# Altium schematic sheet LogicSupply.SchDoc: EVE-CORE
size A4; Organization: Ingenia Motion Control; Address1: Carrer Avila, 124, 2B; Address2: 08018 Barcelona Spain; Address3: www.ingeniamc.com; Address4: www.ingeniamc.com; Documentation: https://doc.ingeniamc.com/x/coAZBg
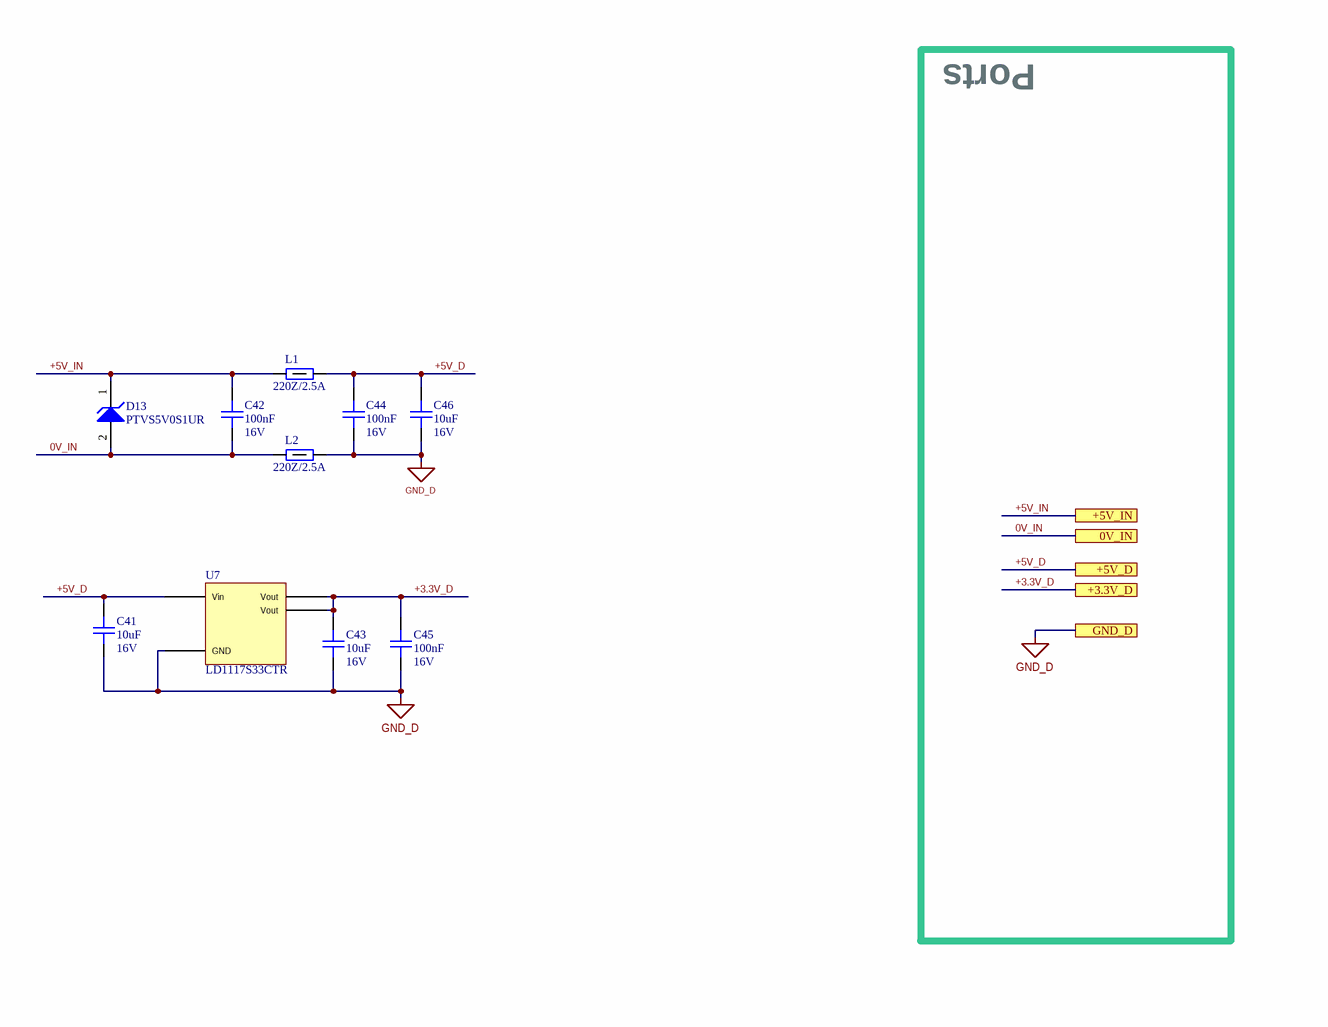
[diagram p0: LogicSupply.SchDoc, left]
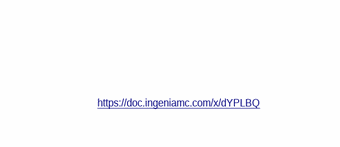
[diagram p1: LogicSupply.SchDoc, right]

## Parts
C41  value 10uF  Voltage: 16V  [C_0805]  (hidden comment: C_0805--10uF--16V)
C42  value 100nF  Voltage: 16V  [C_0402HD]  (hidden comment: C_0402--100nF--16V)
C43  value 10uF  Voltage: 16V  [C_0805]  (hidden comment: C_0805--10uF--16V)
C44  value 100nF  Voltage: 16V  [C_0402HD]  (hidden comment: C_0402--100nF--16V)
C45  value 100nF  Voltage: 16V  [C_0402]  (hidden comment: C_0402--100nF--16V)
C46  value 10uF  Voltage: 16V  [C_0805]  (hidden comment: C_0805--10uF--16V)
D13  Part Number: PTVS5V0S1UR  [SOD123W2]  (hidden comment: TVS2)
L1  value 220Z/2.5A  [L_0603]
L2  value 220Z/2.5A  [L_0603]
U7  LD1117S33CTR  [SOT223-4N]

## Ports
0V_IN, +3.3V_D, +5V_D, +5V_IN, GND_D

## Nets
GND_D: C41.2 C43.2 C44.1 C45.2 C46.2 L2.2 U7.1(GND) ; port GND_D
0V_IN: C42.1 D13.2(A) L2.1 ; port 0V_IN
+3.3V_D: C43.1 C45.1 U7.2(Vout) U7.4(Vout) ; port +3.3V_D
+5V_D: C41.1 C44.2 C46.1 L1.2 U7.3(Vin) ; port +5V_D
+5V_IN: C42.2 D13.1(K) L1.1 ; port +5V_IN

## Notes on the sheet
- Ports
- https://doc.ingeniamc.com/x/dYPLBQ

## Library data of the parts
C41 C43 C46 = C_0805[[/\]]10uF[[/\]]16V: CAP 10 uF 16 V X7S 0805 20% TOL; ManufacturerName: TDK; ManufacturerPN: C2012X7S1C106M125AC; IsPreferred: 0; IngeniaID: 4390; TemperatureMaxC: 125; TemperatureMinC: -55; AlternativePN: CGA4J1X7S1C106K125AC
C42 C44 = C_0402[[/\]]100nF[[/\]]16V: CAP CER 100nF 16V X7R 0402; Part Number: C_0402; ManufacturerName: Murata; ManufacturerPN: GRM155R71C104KA88D; AlternativeManufacturer: Wurth; IsPreferred: 1; IngeniaID: 672; InternalStock: 0; AlternativePN: 885012205037; MTBF55h: 36129613; TemperatureMaxC: 125; TemperatureMinC: -55
C45 = C_0402[[/\]]100nF[[/\]]16V: CAP CER 100nF 16V X7R 0402; ManufacturerName: Murata; ManufacturerPN: GRM155R71C104KA88D; AlternativeManufacturer: Wurth; IsPreferred: 1; IngeniaID: 672; InternalStock: 0; TemperatureMaxC: 125; TemperatureMinC: -55; MTBF55h: 36129613; AlternativePN: 885012205037
D13 = PTVS5V0S1UR: DIODE TVS 5V, 400W, UNIDIRECTIONAL, 5%, SOD123W; ManufacturerName: NXP; ManufacturerPN: PTVS5V0S1UR,115; Value: TVS 5V; IsPreferred: 0; IngeniaID: 1306; TemperatureMaxC: 150; TemperatureMinC: -55
L1 L2 = FB_0603[[/\]]220Z/2.5A: Ferrite Bead 220Ohm@100MHz 2.5A DC, 40mOhm, -55ºC ~ 125ºC 0603; ManufacturerName: Murata; ManufacturerPN: BLM18SG221TN1D; CompletePN: FB_0603--220Z/2.5A; IsPreferred: 1; IsGeneric: 0; IngeniaID: 4428; TemperatureMaxC: 125; TemperatureMinC: -55
U7 = LD1117S33CTR: LDO 3.3V 0.8A Max Input 15V SOT223-3; ManufacturerName: STMicroelectronics; AlternativeManufacturer: Linear Technology; IsPreferred: 1; IsGeneric: 0; IngeniaID: 1636; TemperatureMaxC: 125; TemperatureMinC: -40; AlternativePN: LT1117CST-3.3#PBF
